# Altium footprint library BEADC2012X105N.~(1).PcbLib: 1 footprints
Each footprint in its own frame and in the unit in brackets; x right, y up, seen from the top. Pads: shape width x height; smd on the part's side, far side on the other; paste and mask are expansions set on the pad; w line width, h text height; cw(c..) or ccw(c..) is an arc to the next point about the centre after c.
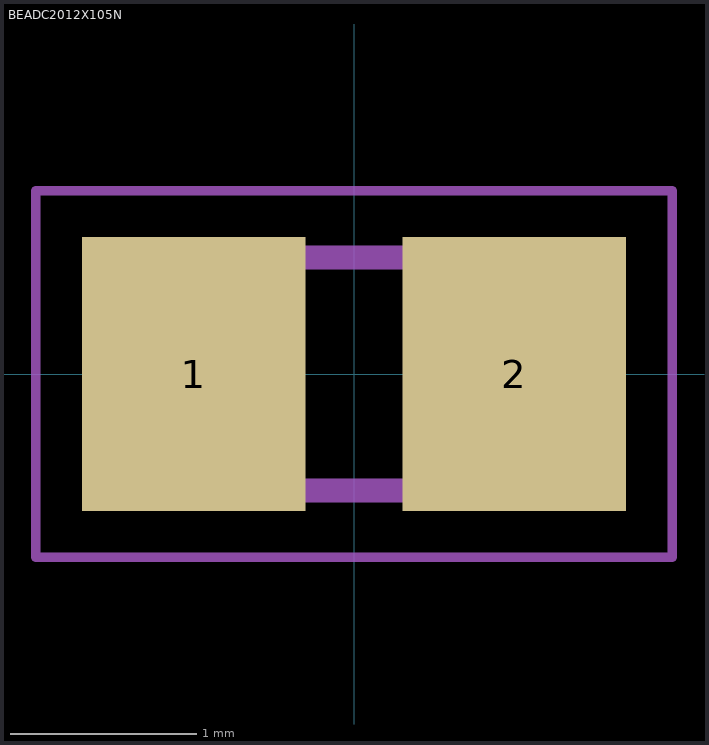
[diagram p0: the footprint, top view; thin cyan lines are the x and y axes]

## BEADC2012X105N [mm]
pads (2):
  rect 1.2x1.47 smd: 1(-0.86,0) 2(0.86,0)
Mechanical 13:
  lines w0.127: -1,-0.625 1,-0.625 1,0.625 -1,0.625 -1,-0.625
Mechanical 15:
  lines w0.05: -1.708,-0.983 1.708,-0.983 1.708,0.983 -1.708,0.983 -1.708,-0.983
